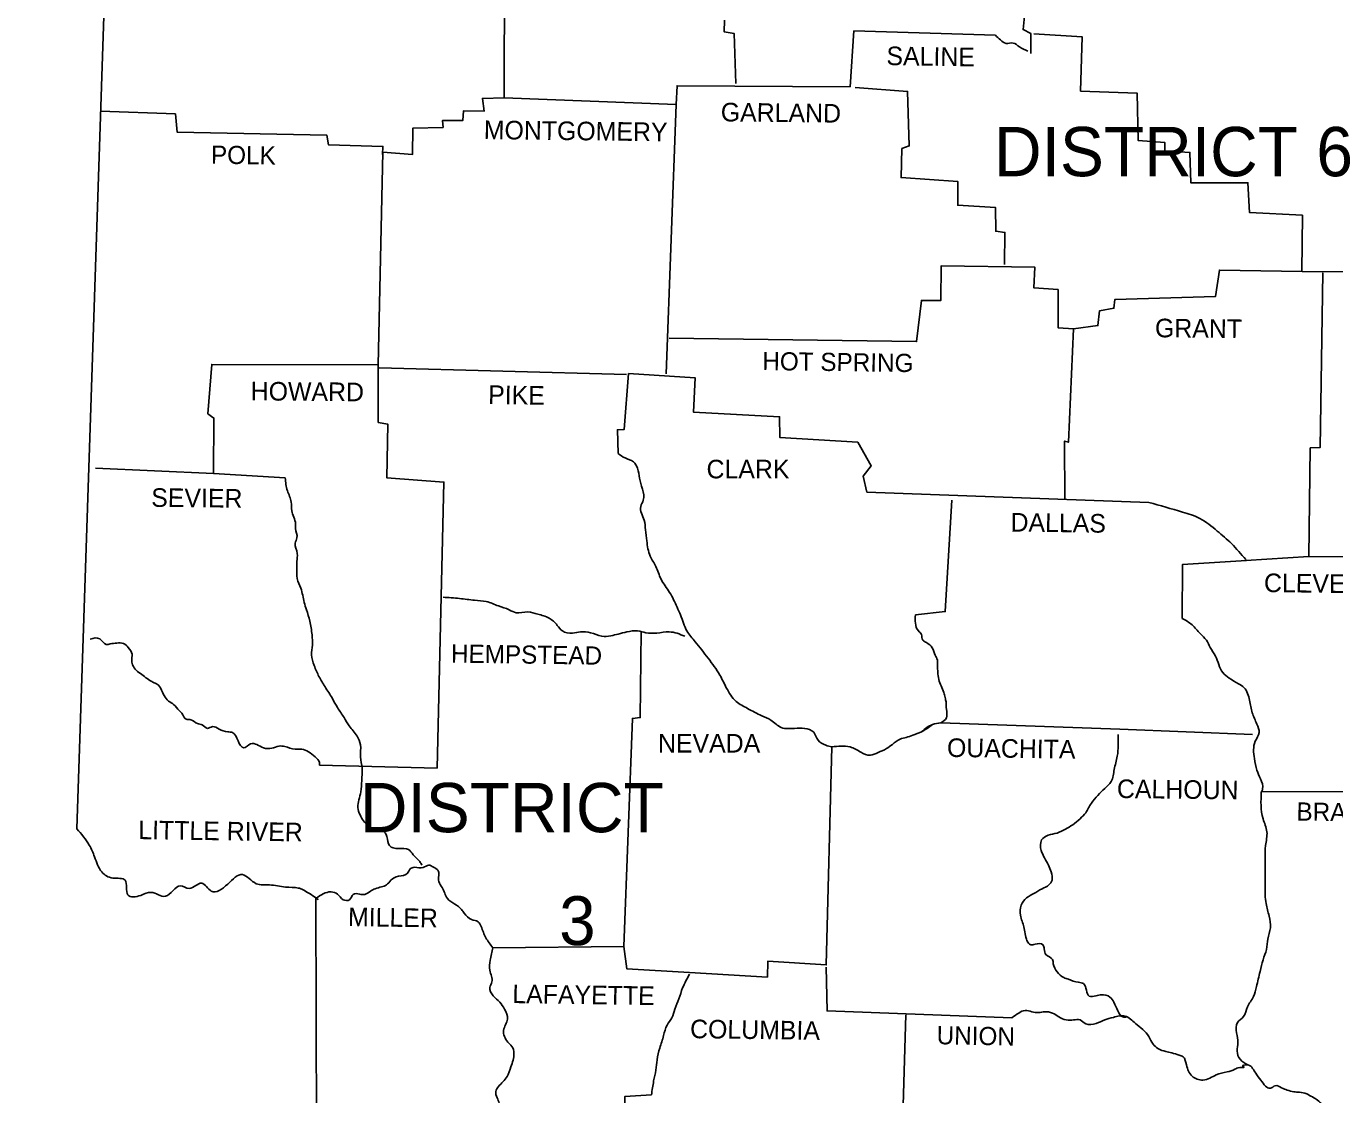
# Model space of a CAD drawing. Extents: x 166 to 3426, y 71 to 2074.
# Drawn here: x 2703.7 to 2999.8, y 1468.2 to 1709.8 of the extents above; entities that cross this region are included whole.
import ezdxf

# ---------------------------------------------------------------- set-up
doc = ezdxf.new("R2010")
doc.units = 0
for name, color, linetype in [('1', 7, 'Continuous'), ('2', 7, 'Continuous'), ('3', 7, 'Continuous')]:
    doc.layers.add(name, color=color, linetype=linetype)

msp = doc.modelspace()

# ---------------------------------------------------------------- linework, layer by layer
at = {"layer": '1'}
for points in [[(2703.71, 1956.42), (2723.96, 1793.81), (2715.15, 1528.37)], [(2812.02, 1750.86), (2811.82, 1693.62), (2806.93, 1693.52), (2807.32, 1690.59), (2802.62, 1690.68), (2802.53, 1688.53), (2797.93, 1688.53), (2798.03, 1686.97), (2791.18, 1686.77), (2791.08, 1680.8), (2784.43, 1681.39), (2783.35, 1633.25), (2745.68, 1633.35), (2744.8, 1622.19), (2746.17, 1621.22), (2746.07, 1608.69), (2719.36, 1609.87)], [(2961.91, 1722.77), (2954.86, 1723.56), (2955.16, 1720.92), (2942.34, 1720.43), (2941.95, 1716.61), (2929.91, 1715.93), (2929.23, 1709.08), (2930.99, 1708.2), (2930.99, 1703.7)], [(2922.97, 1707.81), (2890.97, 1708.78), (2890.09, 1696.16), (2850.96, 1696.36), (2850.76, 1692.15)], [(2861.72, 1711.23), (2861.62, 1708.59), (2863.87, 1708.2), (2864.26, 1696.85)], [(2931.68, 1708.1), (2942.63, 1707.41), (2942.24, 1695.18), (2955.06, 1694.69), (2955.26, 1684.03), (2961.32, 1683.54), (2961.32, 1681.68), (2967, 1681.29), (2967.19, 1674.44), (2980.11, 1674.44), (2980.5, 1667.69), (2992.44, 1667.1), (2992.34, 1654.38)], [(2850.76, 1692.15), (2811.82, 1693.62)], [(2891.27, 1695.97), (2903.11, 1695.09), (2903.5, 1682.76), (2901.83, 1682.17), (2901.64, 1675.62), (2914.46, 1674.74), (2914.46, 1669.35), (2922.97, 1668.86), (2923.07, 1663.48), (2925.12, 1663.19), (2925.02, 1655.95)], [(2720.54, 1690.59), (2737.46, 1690), (2737.85, 1685.89), (2771.71, 1685.2), (2772.1, 1683.05), (2784.43, 1682.66), (2784.33, 1680.8)], [(2850.76, 1692.15), (2848.51, 1631.2)], [(3109.06, 1665.64), (3072.08, 1666.61), (3071.88, 1654.58), (2997.03, 1654.29)], [(2849.2, 1639.32), (2905.16, 1638.53), (2906.24, 1647.83), (2910.64, 1647.83), (2910.74, 1655.66), (2931.87, 1655.36), (2931.68, 1650.67), (2937.16, 1650.27), (2937.16, 1641.66), (2940.68, 1641.37)], [(2940.68, 1641.37), (2946.16, 1642.15), (2946.55, 1645.48), (2949.78, 1646.07), (2949.97, 1648.02), (2972.77, 1648.71), (2973.65, 1654.68), (2997.03, 1654.29)], [(2997.03, 1654.09), (2996.45, 1614.56), (2994.2, 1614.47), (2993.9, 1589.91)], [(2940.68, 1641.37), (2939.5, 1615.74), (2938.62, 1616.03), (2938.72, 1602.72)], [(2783.35, 1633.25), (2783.35, 1620.24), (2785.5, 1619.85), (2785.31, 1607.71), (2798.22, 1606.74), (2796.66, 1542.06), (2770.04, 1542.75)], [(2783.55, 1632.57), (2839.51, 1631.1)], [(2837.65, 1613.19), (2837.46, 1618.57), (2839.02, 1618.67), (2840, 1631.29), (2855.07, 1630.32), (2854.68, 1622.59), (2874.15, 1621.51), (2874.24, 1616.81), (2891.85, 1615.74), (2894.89, 1610.45), (2893.03, 1608.11), (2893.91, 1604.49), (2957.7, 1602.14)], [(2746.07, 1608.69), (2762.31, 1607.71)], [(2913.09, 1602.63), (2911.62, 1577.48), (2904.87, 1576.7)], [(2993.9, 1589.91), (2979.62, 1589.03)], [(2993.9, 1589.91), (3028.54, 1589.71)], [(2979.81, 1589.03), (2965.33, 1588.15), (2965.24, 1575.92)], [(2842.84, 1572.98), (2842.64, 1553.51), (2840.88, 1553.31), (2838.92, 1501.75)], [(2910.64, 1552.34), (2951.15, 1550.87), (2981.18, 1549.69)], [(2885.98, 1546.86), (2884.71, 1497.55), (2871.5, 1498.43), (2871.41, 1494.81), (2853.79, 1495.88)], [(2983.14, 1536.68), (3027.36, 1536.78)], [(2769.26, 1512.61), (2769.46, 1433.46), (3128.04, 1432.87)], [(2853.79, 1495.88), (2839.61, 1496.67), (2838.92, 1501.75), (2809.28, 1501.46)], [(2926.69, 1485.61), (2884.91, 1487.17), (2884.71, 1497.06)], [(2902.72, 1486.29), (2901.15, 1432.58)], [(2845.18, 1468.19), (2839.12, 1467.8), (2838.43, 1433.36)]]:
    msp.add_lwpolyline(points, dxfattribs=at)
for points in [[(2930.31, 1704.19), (2928.45, 1705.16), (2926.98, 1706.04), (2925.41, 1705.95), (2924.14, 1706.73), (2922.97, 1707.81)], [(2837.65, 1613.19), (2839.22, 1612.21), (2841.08, 1611.33), (2842.05, 1609.87), (2842.45, 1607.62), (2843.13, 1605.17), (2843.33, 1602.63), (2842.74, 1601.26), (2843.52, 1598.13), (2843.82, 1595.97), (2844.11, 1593.43), (2844.89, 1590.01), (2846.16, 1587.66), (2847.34, 1584.82), (2849.29, 1581.79), (2850.96, 1578.46), (2851.74, 1576.7), (2853.21, 1573.08), (2855.07, 1570.63), (2858, 1566.91), (2860.64, 1563.1), (2862.11, 1560.26), (2864.36, 1557.13), (2866.91, 1555.57), (2870.13, 1553.9), (2872.19, 1552.92), (2874.54, 1551.26), (2877.57, 1551.06), (2879.82, 1551.06), (2881.88, 1550.18), (2882.85, 1548.42), (2884.61, 1547.25), (2885.98, 1546.86)], [(2762.31, 1607.71), (2762.8, 1604.78), (2763.68, 1602.24), (2763.78, 1600.28), (2764.66, 1597.34), (2764.66, 1596.27), (2764.96, 1594.11), (2764.56, 1592.94), (2765.05, 1590.59), (2764.96, 1588.83), (2764.96, 1587.36), (2765.05, 1584.92), (2765.84, 1582.76), (2766.62, 1579.54), (2767.11, 1577.87), (2767.89, 1575.33), (2768.38, 1572.2), (2768.48, 1569.85), (2768.28, 1567.7), (2768.87, 1565.25), (2769.95, 1562.81), (2771.32, 1560.46), (2772.98, 1557.82), (2774.15, 1555.76), (2775.62, 1553.51), (2776.79, 1551.65), (2778.56, 1549.3), (2779.34, 1547.35), (2779.34, 1544.61), (2779.73, 1542.06), (2779.63, 1539.23), (2779.44, 1536.68), (2778.75, 1533.16), (2779.24, 1531.5), (2781.1, 1529.05), (2782.27, 1528.37), (2784.33, 1527.97), (2785.31, 1526.6), (2785.89, 1524.55), (2787.95, 1523.86), (2790.2, 1523.67), (2791.27, 1522.49), (2792.74, 1520.93), (2793.23, 1520.15)], [(2957.7, 1602.14), (2965.33, 1599.98), (2969.25, 1598.52), (2973.16, 1595.68), (2976.39, 1592.84), (2979.62, 1589.22)], [(2798.03, 1580.71), (2801.74, 1580.42), (2805.17, 1580.03), (2807.81, 1579.73), (2810.55, 1578.75), (2813, 1577.87), (2814.56, 1577.19), (2817.2, 1577.38), (2819.45, 1576.89), (2822, 1576.01), (2823.86, 1574.35), (2825.03, 1573.08), (2827.28, 1572.59), (2829.14, 1572.88), (2831.39, 1572.69), (2833.93, 1571.9), (2835.99, 1572), (2837.65, 1572.39), (2839.61, 1572.88), (2842.05, 1573.08), (2843.91, 1572.69), (2846.36, 1572.59), (2849.2, 1572.88), (2852.72, 1571.9)], [(2904.87, 1576.7), (2904.87, 1574.84), (2905.55, 1573.08), (2906.24, 1572.3), (2906.53, 1571.02), (2907.41, 1570.44), (2908.68, 1569.26), (2909.37, 1567.6), (2909.86, 1566.52), (2909.86, 1565.15), (2909.96, 1563.78), (2910.15, 1562.12), (2911.33, 1559.19), (2911.62, 1558.01), (2911.81, 1557.03), (2911.91, 1555.37), (2911.91, 1553.41), (2910.64, 1552.34)], [(2965.24, 1575.92), (2967.49, 1574.45), (2969.34, 1572.49), (2970.71, 1571.02), (2971.59, 1569.36), (2972.77, 1567.4), (2974.43, 1563.69), (2975.9, 1562.41), (2977.95, 1561.14), (2979.23, 1560.26), (2980.5, 1557.42), (2981.09, 1554.59), (2982.16, 1552.04), (2982.65, 1550.09), (2981.77, 1548.13), (2981.57, 1544.22), (2982.16, 1541.57), (2982.94, 1539.62), (2983.43, 1537.37), (2983.14, 1536.68)], [(2718.19, 1571.22), (2720.34, 1571.32), (2721.81, 1570.05), (2722.69, 1570.14), (2724.25, 1570.34), (2725.72, 1570.24), (2726.8, 1569.36), (2727.68, 1567.8), (2727.58, 1566.33), (2727.68, 1565.74), (2728.36, 1564.47), (2729.54, 1563.49), (2730.81, 1562.51), (2731.98, 1561.73), (2733.94, 1560.46), (2734.14, 1560.07), (2734.92, 1558.5), (2735.9, 1557.23), (2737.07, 1556.45), (2738.34, 1555.08), (2738.93, 1554.49), (2739.91, 1553.12), (2740.98, 1553.02), (2742.45, 1552.14), (2743.53, 1551.85), (2744.7, 1551.06), (2745.88, 1551.46), (2747.34, 1550.87), (2749.3, 1550.28), (2750.38, 1550.09), (2751.65, 1548.23), (2752.92, 1546.66), (2754.49, 1547.54), (2757.42, 1546.66), (2759.28, 1546.56), (2760.94, 1547.05), (2762.22, 1546.96), (2764.56, 1546.37), (2766.03, 1546.37), (2767.6, 1545.78), (2769.06, 1544.61), (2770.04, 1543.34), (2770.04, 1542.75)], [(2908.78, 1551.95), (2906.24, 1550.28), (2904.28, 1549.5), (2902.81, 1549.01), (2901.44, 1548.62), (2899.68, 1547.44), (2898.31, 1546.47), (2896.45, 1545.59), (2894.69, 1545), (2892.54, 1545.68), (2891.37, 1546.37), (2890.09, 1546.86), (2885.98, 1546.86)], [(2906.24, 1550.28), (2908.78, 1551.95), (2910.64, 1552.34)], [(2950.75, 1549.69), (2950.56, 1544.8), (2949.87, 1541.77), (2949.19, 1539.03), (2947.72, 1537.46), (2946.16, 1535.9), (2944.69, 1534.14), (2943.42, 1531.99), (2942.14, 1530.62), (2940.48, 1529.25), (2938.82, 1528.27), (2936.96, 1527.39), (2934.9, 1526.9), (2933.44, 1525.82), (2933.34, 1523.47), (2935, 1520.15), (2935.59, 1518.58), (2935.79, 1516.72), (2935.1, 1515.65), (2933.53, 1514.77), (2931.68, 1513.69), (2930.01, 1512.71), (2928.84, 1511.05), (2928.64, 1508.8), (2929.43, 1506.16), (2929.72, 1504.59), (2930.99, 1502.14), (2931.97, 1502.24), (2933.73, 1502.14), (2933.93, 1501.65), (2934.02, 1501.17), (2934.42, 1499.89), (2935.88, 1498.82), (2936.08, 1497.84), (2936.96, 1495.98), (2938.43, 1494.71), (2939.5, 1494.32), (2941.75, 1493.63), (2942.93, 1493.34), (2944.2, 1490.5), (2945.77, 1490.6), (2946.94, 1490.79), (2948.9, 1490.31), (2949.78, 1489.13), (2950.66, 1487.17), (2951.83, 1485.8), (2952.61, 1485.8)], [(2983.14, 1536.68), (2983.53, 1530.62), (2984.41, 1527.68), (2984.12, 1524.55), (2984.02, 1521.52), (2984.02, 1518.78), (2984.02, 1516.14), (2984.02, 1513.4), (2984.22, 1511.44), (2984.9, 1508.6), (2985.19, 1505.96), (2984.61, 1503.42), (2984.31, 1501.07), (2983.53, 1498.72), (2982.85, 1496.08), (2982.06, 1492.65), (2981.38, 1490.4), (2980.01, 1488.06), (2979.13, 1485.9), (2977.76, 1484.53), (2977.56, 1482.18), (2977.86, 1480.03), (2977.66, 1478.08), (2978.35, 1476.22), (2980.11, 1474.94)], [(2715.15, 1528.37), (2717.99, 1524.65), (2719.17, 1522.01), (2720.83, 1518.58), (2723.28, 1517.21), (2726.11, 1516.72), (2726.7, 1513.4), (2729.63, 1513.3), (2731.98, 1513.98), (2735.21, 1513.1), (2738.64, 1515.45), (2740.59, 1514.86), (2743.43, 1516.04), (2745.58, 1514.28), (2749.3, 1515.84), (2752.63, 1517.99), (2755.76, 1515.94), (2758.79, 1515.65), (2762.41, 1515.16), (2765.25, 1514.96), (2767.79, 1513.69), (2769.65, 1512.42), (2769.26, 1512.61)], [(2769.26, 1512.61), (2772.68, 1514.08), (2774.15, 1513.59), (2775.42, 1512.32), (2776.89, 1512.32), (2777.67, 1513.49), (2779.14, 1513.59), (2780.32, 1513.49), (2781.59, 1514.28), (2782.66, 1514.77), (2784.13, 1515.25), (2785.21, 1515.65), (2786.19, 1516.72), (2787.95, 1517.6), (2790, 1518.29), (2790.59, 1519.27), (2791.57, 1519.66), (2793.52, 1519.56), (2794.8, 1520.15), (2795.87, 1519.66), (2796.85, 1518.97), (2797.05, 1516.43), (2797.83, 1515.06), (2799, 1512.61), (2800.67, 1511.34), (2802.23, 1510.07), (2802.82, 1509.29), (2804.48, 1507.82), (2805.95, 1507.33), (2806.64, 1506.25), (2807.71, 1503.71), (2809.28, 1501.46)], [(2809.28, 1501.46), (2808.69, 1498.62), (2808.59, 1496.37), (2809.08, 1493.73), (2808.59, 1492.46), (2809.38, 1490.6), (2810.84, 1489.13), (2811.92, 1487.57), (2812.6, 1485.32), (2811.72, 1482.77), (2812.7, 1480.13), (2813.58, 1479.15), (2814.07, 1477.59), (2813.39, 1474.55), (2812.51, 1472.3), (2810.55, 1470.05), (2809.96, 1468.98), (2810.26, 1467.51), (2810.74, 1465.16), (2810.26, 1464.48), (2808.98, 1462.81), (2808.59, 1460.95), (2807.71, 1459.39), (2806.73, 1456.55), (2805.46, 1454.2), (2805.27, 1451.56), (2803.31, 1451.56), (2801.06, 1451.56), (2799, 1450.09), (2797.15, 1450), (2794.89, 1449.11), (2793.52, 1447.26), (2793.04, 1445.2), (2792.45, 1443.24), (2793.04, 1439.92), (2793.92, 1437.57), (2794.6, 1435.71), (2795.78, 1432.68)], [(2845.18, 1468.19), (2845.67, 1471.32), (2846.16, 1473.77), (2846.46, 1476.12), (2847.04, 1478.76), (2847.92, 1481.6), (2848.71, 1483.95), (2849.78, 1485.61), (2850.47, 1487.57), (2851.35, 1489.91), (2852.23, 1492.36), (2853.79, 1495.49)], [(2926.69, 1485.61), (2928.25, 1486.69), (2929.72, 1487.27), (2931.19, 1486.98), (2932.75, 1486.78), (2934.12, 1486.98), (2935.88, 1486.69), (2937.35, 1485.8), (2939.01, 1485.12), (2940.68, 1485.12), (2942.14, 1485.12), (2943.42, 1484.24), (2945.77, 1484.34), (2947.72, 1485.12), (2949.68, 1485.71), (2952.32, 1486), (2954.67, 1484.34), (2956.33, 1482.97), (2957.7, 1481.4), (2958.68, 1479.64), (2959.76, 1478.66), (2961.52, 1477.98), (2962.89, 1477.68), (2964.55, 1477.19), (2965.43, 1476.8), (2966.21, 1474.94), (2967.49, 1472.4), (2969.93, 1471.52), (2972.96, 1472.69), (2975.41, 1473.38), (2977.17, 1473.97), (2978.25, 1474.36), (2979.23, 1474.46), (2978.93, 1474.65), (2980.11, 1474.94), (2981.18, 1474.16), (2981.87, 1473.09), (2983.04, 1471.52), (2984.12, 1470.15), (2985.19, 1469.66), (2986.27, 1470.25), (2987.74, 1469.76), (2989.01, 1469.27), (2990.48, 1468.88), (2991.75, 1468.78), (2993.41, 1468.39), (2994.69, 1467.7), (2995.86, 1467.02), (2997.03, 1465.75), (2998.21, 1463.79), (2998.6, 1462.23), (2999.97, 1460.66), (3001.24, 1460.66), (3003.1, 1458.12), (3003.78, 1457.14), (3005.25, 1455.38), (3006.33, 1455.38), (3008.38, 1454.98)]]:
    msp.add_spline(points, degree=3, dxfattribs=at)

# ---------------------------------------------------------------- texts
at = {"layer": '2'}
for s, height, rotation, p in [('SALINE', 4.207, 359.1491, (2898.31, 1701.05)), ('GARLAND', 4.207, 359.3658, (2860.84, 1688.33)), ('MONTGOMERY', 4.207, 359.2944, (2807.22, 1684.32)), ('POLK', 4.108, 359.2152, (2745.49, 1678.75)), ('GRANT', 4.207, 359.4032, (2959.07, 1639.51)), ('HOT SPRING', 4.109, 359.2216, (2870.23, 1632.08)), ('HOWARD', 4.207, 359.5145, (2754.49, 1625.23)), ('PIKE', 4.206, 359.0452, (2808.2, 1624.44)), ('SEVIER', 4.207, 359.4271, (2731.98, 1601.16)), ('DALLAS', 4.206, 359.2462, (2926.39, 1595.58)), ('CLEVELAND', 4.207, 359.3377, (2983.73, 1581.88)), ('HEMPSTEAD', 4.108, 359.1885, (2799.79, 1565.94)), ('OUACHITA', 4.207, 359.2043, (2912.01, 1544.61)), ('CALHOUN', 4.207, 359.3634, (2950.46, 1535.31)), ('BRADLEY', 4.108, 359.1449, (2991.07, 1530.22)), ('LITTLE RIVER', 4.2073, 359.1697, (2729.05, 1526.02)), ('MILLER', 4.206, 359.1319, (2776.5, 1506.35)), ('LAFAYETTE', 4.206, 359.1839, (2813.68, 1488.94)), ('COLUMBIA', 4.206, 359.2125, (2853.89, 1481.01)), ('UNION', 4.109, 358.9584, (2909.66, 1479.64))]:
    msp.add_text(s, height=height, rotation=rotation, dxfattribs=at).set_placement(p)
for s, p in [('CLARK', (2857.63, 1607.59)), ('NEVADA', (2846.65, 1545.59))]:
    msp.add_text(s, height=4.207, dxfattribs=at).set_placement(p)
at = {"layer": '3'}
for s, height, p in [('DISTRICT 6', 11.154, (2922.67, 1675.91)), ('DISTRICT', 11.154, (2779.19, 1527.57)), ('3', 11.06, (2824.3, 1502.04))]:
    msp.add_text(s, height=height, dxfattribs=at).set_placement(p)

doc.saveas('drawing.dxf')
